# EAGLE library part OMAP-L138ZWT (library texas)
OMAP-L138 Low-Power Applications Processor Auto generated by make-symbol-device-package-bsdl.ulp Rev. 30 Source: sprm376a.bsm http://focus.ti.com/lit/ds/symlink/omap-l138.pdf Connect-List generated from OMAPL138ZWT.DEV Variant '' with connect-device-split-symbol-03.ulp
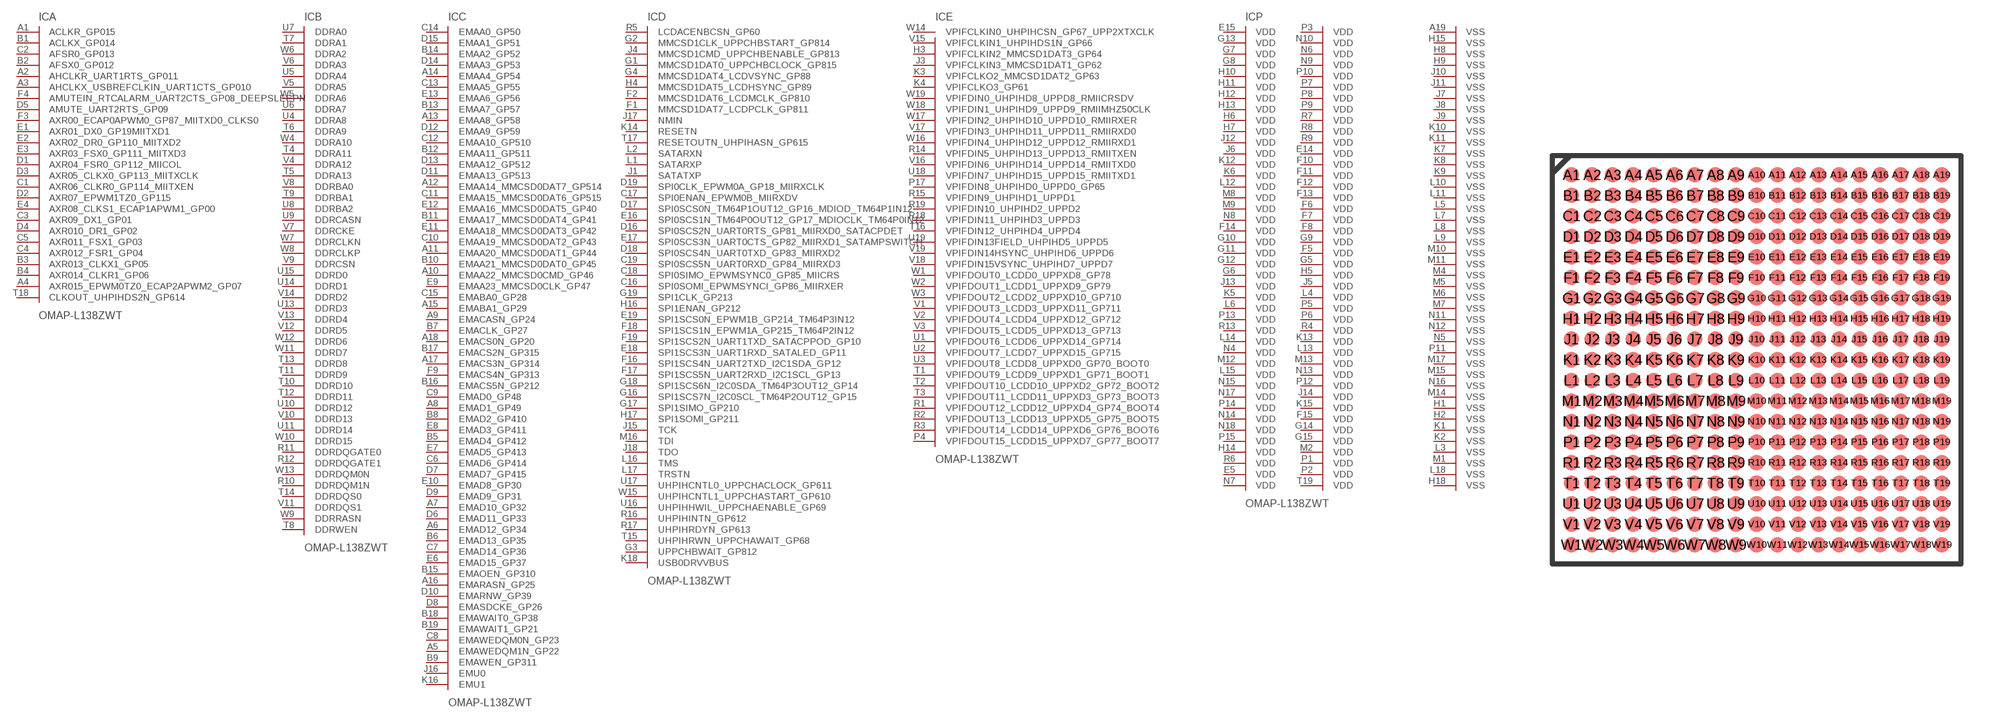
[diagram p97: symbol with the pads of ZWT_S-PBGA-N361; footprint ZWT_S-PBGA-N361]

Designator prefix IC; gates A=OMAPL138Z-A B=OMAPL138Z-B C=OMAPL138Z-C D=OMAPL138Z-D E=OMAPL138Z-E P=OMAPL138Z-P

## OMAP-L138ZWT (OC_FARNELL: unknown; OC_NEWARK: unknown)  [ZWT_S-PBGA-N361]
A1  A:ACLKR_GP015
A2  A:AHCLKR_UART1RTS_GP011
A3  A:AHCLKX_USBREFCLKIN_UART1CTS_GP010
A4  A:AXR015_EPWM0TZ0_ECAP2APWM2_GP07
A5  C:EMAWEDQM1N_GP22
A6  C:EMAD12_GP34
A7  C:EMAD10_GP32
A8  C:EMAD1_GP49
A9  C:EMACASN_GP24
A10  C:EMAA22_MMCSD0CMD_GP46
A11  C:EMAA20_MMCSD0DAT1_GP44
A12  C:EMAA14_MMCSD0DAT7_GP514
A13  C:EMAA8_GP58
A14  C:EMAA4_GP54
A15  C:EMABA1_GP29
A16  C:EMARASN_GP25
A17  C:EMACS3N_GP314
A18  C:EMACS0N_GP20
A19  P:VSS  pwr
B1  A:ACLKX_GP014
B2  A:AFSX0_GP012
B3  A:AXR013_CLKX1_GP05
B4  A:AXR014_CLKR1_GP06
B5  C:EMAD4_GP412
B6  C:EMAD13_GP35
B7  C:EMACLK_GP27
B8  C:EMAD2_GP410
B9  C:EMAWEN_GP311
B10  C:EMAA21_MMCSD0DAT0_GP45
B11  C:EMAA17_MMCSD0DAT4_GP41
B12  C:EMAA11_GP511
B13  C:EMAA7_GP57
B14  C:EMAA2_GP52
B15  C:EMAOEN_GP310
B16  C:EMACS5N_GP212
B17  C:EMACS2N_GP315
B18  C:EMAWAIT0_GP38
B19  C:EMAWAIT1_GP21
C1  A:AXR06_CLKR0_GP114_MIITXEN
C2  A:AFSR0_GP013
C3  A:AXR09_DX1_GP01
C4  A:AXR012_FSR1_GP04
C5  A:AXR011_FSX1_GP03
C6  C:EMAD6_GP414
C7  C:EMAD14_GP36
C8  C:EMAWEDQM0N_GP23
C9  C:EMAD0_GP48
C10  C:EMAA19_MMCSD0DAT2_GP43
C11  C:EMAA15_MMCSD0DAT6_GP515
C12  C:EMAA10_GP510
C13  C:EMAA5_GP55
C14  C:EMAA0_GP50
C15  C:EMABA0_GP28
C16  D:SPI0SOMI_EPWMSYNCI_GP86_MIIRXER
C17  D:SPI0ENAN_EPWM0B_MIIRXDV
C18  D:SPI0SIMO_EPWMSYNC0_GP85_MIICRS
C19  D:SPI0SCS5N_UART0RXD_GP84_MIIRXD3
D1  A:AXR04_FSR0_GP112_MIICOL
D2  A:AXR07_EPWM1TZ0_GP115
D3  A:AXR05_CLKX0_GP113_MIITXCLK
D4  A:AXR010_DR1_GP02
D5  A:AMUTE_UART2RTS_GP09
D6  C:EMAD11_GP33
D7  C:EMAD7_GP415
D8  C:EMASDCKE_GP26
D9  C:EMAD9_GP31
D10  C:EMARNW_GP39
D11  C:EMAA13_GP513
D12  C:EMAA9_GP59
D13  C:EMAA12_GP512
D14  C:EMAA3_GP53
D15  C:EMAA1_GP51
D16  D:SPI0SCS2N_UART0RTS_GP81_MIIRXD0_SATACPDET
D17  D:SPI0SCS0N_TM64P1OUT12_GP16_MDIOD_TM64P1IN12
D18  D:SPI0SCS4N_UART0TXD_GP83_MIIRXD2
D19  D:SPI0CLK_EPWM0A_GP18_MIIRXCLK
E1  A:AXR01_DX0_GP19MIITXD1
E2  A:AXR02_DR0_GP110_MIITXD2
E3  A:AXR03_FSX0_GP111_MIITXD3
E4  A:AXR08_CLKS1_ECAP1APWM1_GP00
E5  P:VDD  pwr
E6  C:EMAD15_GP37
E7  C:EMAD5_GP413
E8  C:EMAD3_GP411
E9  C:EMAA23_MMCSD0CLK_GP47
E10  C:EMAD8_GP30
E11  C:EMAA18_MMCSD0DAT3_GP42
E12  C:EMAA16_MMCSD0DAT5_GP40
E13  C:EMAA6_GP56
E14  P:VDD  pwr
E15  P:VDD  pwr
E16  D:SPI0SCS1N_TM64P0OUT12_GP17_MDIOCLK_TM64P0IN12
E17  D:SPI0SCS3N_UART0CTS_GP82_MIIRXD1_SATAMPSWITCH
E18  D:SPI1SCS3N_UART1RXD_SATALED_GP11
E19  D:SPI1SCS0N_EPWM1B_GP214_TM64P3IN12
F1  D:MMCSD1DAT7_LCDPCLK_GP811
F2  D:MMCSD1DAT6_LCDMCLK_GP810
F3  A:AXR00_ECAP0APWM0_GP87_MIITXD0_CLKS0
F4  A:AMUTEIN_RTCALARM_UART2CTS_GP08_DEEPSLEEPN
F5  P:VDD  pwr
F6  P:VDD  pwr
F7  P:VDD  pwr
F8  P:VDD  pwr
F9  C:EMACS4N_GP313
F10  P:VDD  pwr
F11  P:VDD  pwr
F12  P:VDD  pwr
F13  P:VDD  pwr
F14  P:VDD  pwr
F15  P:VDD  pwr
F16  D:SPI1SCS4N_UART2TXD_I2C1SDA_GP12
F17  D:SPI1SCS5N_UART2RXD_I2C1SCL_GP13
F18  D:SPI1SCS1N_EPWM1A_GP215_TM64P2IN12
F19  D:SPI1SCS2N_UART1TXD_SATACPPOD_GP10
G1  D:MMCSD1DAT0_UPPCHBCLOCK_GP815
G2  D:MMCSD1CLK_UPPCHBSTART_GP814
G3  D:UPPCHBWAIT_GP812
G4  D:MMCSD1DAT4_LCDVSYNC_GP88
G5  P:VDD  pwr
G6  P:VDD  pwr
G7  P:VDD  pwr
G8  P:VDD  pwr
G9  P:VDD  pwr
G10  P:VDD  pwr
G11  P:VDD  pwr
G12  P:VDD  pwr
G13  P:VDD  pwr
G14  P:VDD  pwr
G15  P:VDD  pwr
G16  D:SPI1SCS7N_I2C0SCL_TM64P2OUT12_GP15
G17  D:SPI1SIMO_GP210
G18  D:SPI1SCS6N_I2C0SDA_TM64P3OUT12_GP14
G19  D:SPI1CLK_GP213
H1  P:VSS  pwr
H2  P:VSS  pwr
H3  E:VPIFCLKIN2_MMCSD1DAT3_GP64
H4  D:MMCSD1DAT5_LCDHSYNC_GP89
H5  P:VDD  pwr
H6  P:VDD  pwr
H7  P:VDD  pwr
H8  P:VSS  pwr
H9  P:VSS  pwr
H10  P:VDD  pwr
H11  P:VDD  pwr
H12  P:VDD  pwr
H13  P:VDD  pwr
H14  P:VDD  pwr
H15  P:VSS  pwr
H16  D:SPI1ENAN_GP212
H17  D:SPI1SOMI_GP211
H18  P:VSS  pwr
J1  D:SATATXP  hiz
J3  E:VPIFCLKIN3_MMCSD1DAT1_GP62
J4  D:MMCSD1CMD_UPPCHBENABLE_GP813
J5  P:VDD  pwr
J6  P:VDD  pwr
J7  P:VSS  pwr
J8  P:VSS  pwr
J9  P:VSS  pwr
J10  P:VSS  pwr
J11  P:VSS  pwr
J12  P:VDD  pwr
J13  P:VDD  pwr
J14  P:VDD  pwr
J15  D:TCK  in
J16  C:EMU0
J17  D:NMIN  in
J18  D:TDO  out
K1  P:VSS  pwr
K2  P:VSS  pwr
K3  E:VPIFCLKO2_MMCSD1DAT2_GP63
K4  E:VPIFCLKO3_GP61
K5  P:VDD  pwr
K6  P:VDD  pwr
K7  P:VSS  pwr
K8  P:VSS  pwr
K9  P:VSS  pwr
K10  P:VSS  pwr
K11  P:VSS  pwr
K12  P:VDD  pwr
K13  P:VDD  pwr
K14  D:RESETN  in
K15  P:VDD  pwr
K16  C:EMU1
K18  D:USB0DRVVBUS
L1  D:SATARXP  in
L2  D:SATARXN  in
L3  P:VSS  pwr
L4  P:VDD  pwr
L5  P:VSS  pwr
L6  P:VDD  pwr
L7  P:VSS  pwr
L8  P:VSS  pwr
L9  P:VSS  pwr
L10  P:VSS  pwr
L11  P:VSS  pwr
L12  P:VDD  pwr
L13  P:VDD  pwr
L14  P:VDD  pwr
L15  P:VDD  pwr
L16  D:TMS  in
L17  D:TRSTN  in
L18  P:VSS  pwr
M1  P:VSS  pwr
M2  P:VDD  pwr
M4  P:VSS  pwr
M5  P:VSS  pwr
M6  P:VSS  pwr
M7  P:VSS  pwr
M8  P:VDD  pwr
M9  P:VDD  pwr
M10  P:VSS  pwr
M11  P:VSS  pwr
M12  P:VDD  pwr
M13  P:VDD  pwr
M14  P:VSS  pwr
M15  P:VSS  pwr
M16  D:TDI  in
M17  P:VSS  pwr
N4  P:VDD  pwr
N5  P:VSS  pwr
N6  P:VDD  pwr
N7  P:VDD  pwr
N8  P:VDD  pwr
N9  P:VDD  pwr
N10  P:VDD  pwr
N11  P:VSS  pwr
N12  P:VSS  pwr
N13  P:VDD  pwr
N14  P:VDD  pwr
N15  P:VDD  pwr
N16  P:VSS  pwr
N17  P:VDD  pwr
N18  P:VDD  pwr
P1  P:VDD  pwr
P2  P:VDD  pwr
P3  P:VDD  pwr
P4  E:VPIFDOUT15_LCDD15_UPPXD7_GP77_BOOT7
P5  P:VDD  pwr
P6  P:VDD  pwr
P7  P:VDD  pwr
P8  P:VDD  pwr
P9  P:VDD  pwr
P10  P:VDD  pwr
P11  P:VSS  pwr
P12  P:VDD  pwr
P13  P:VDD  pwr
P14  P:VDD  pwr
P15  P:VDD  pwr
P17  E:VPIFDIN8_UHPIHD0_UPPD0_GP65
R1  E:VPIFDOUT12_LCDD12_UPPXD4_GP74_BOOT4
R2  E:VPIFDOUT13_LCDD13_UPPXD5_GP75_BOOT5
R3  E:VPIFDOUT14_LCDD14_UPPXD6_GP76_BOOT6
R4  P:VDD  pwr
R5  D:LCDACENBCSN_GP60
R6  P:VDD  pwr
R7  P:VDD  pwr
R8  P:VDD  pwr
R9  P:VDD  pwr
R10  B:DDRDQM1N
R11  B:DDRDQGATE0
R12  B:DDRDQGATE1
R13  P:VDD  pwr
R14  E:VPIFDIN5_UHPIHD13_UPPD13_RMIITXEN
R15  E:VPIFDIN9_UHPIHD1_UPPD1
R16  D:UHPIHINTN_GP612
R17  D:UHPIHRDYN_GP613
R18  E:VPIFDIN11_UHPIHD3_UPPD3
R19  E:VPIFDIN10_UHPIHD2_UPPD2
T1  E:VPIFDOUT9_LCDD9_UPPXD1_GP71_BOOT1
T2  E:VPIFDOUT10_LCDD10_UPPXD2_GP72_BOOT2
T3  E:VPIFDOUT11_LCDD11_UPPXD3_GP73_BOOT3
T4  B:DDRA11
T5  B:DDRA13
T6  B:DDRA9
T7  B:DDRA1
T8  B:DDRWEN
T9  B:DDRBA1
T10  B:DDRD10
T11  B:DDRD9
T12  B:DDRD11
T13  B:DDRD8
T14  B:DDRDQS0
T15  D:UHPIHRWN_UPPCHAWAIT_GP68
T16  E:VPIFDIN12_UHPIHD4_UPPD4
T17  D:RESETOUTN_UHPIHASN_GP615
T18  A:CLKOUT_UHPIHDS2N_GP614
T19  P:VDD  pwr
U1  E:VPIFDOUT6_LCDD6_UPPXD14_GP714
U2  E:VPIFDOUT7_LCDD7_UPPXD15_GP715
U3  E:VPIFDOUT8_LCDD8_UPPXD0_GP70_BOOT0
U4  B:DDRA8
U5  B:DDRA4
U6  B:DDRA7
U7  B:DDRA0
U8  B:DDRBA2
U9  B:DDRCASN
U10  B:DDRD12
U11  B:DDRD14
U13  B:DDRD3
U14  B:DDRD1
U15  B:DDRD0
U16  D:UHPIHHWIL_UPPCHAENABLE_GP69
U17  D:UHPIHCNTL0_UPPCHACLOCK_GP611
U18  E:VPIFDIN7_UHPIHD15_UPPD15_RMIITXD1
U19  E:VPIFDIN13FIELD_UHPIHD5_UPPD5
V1  E:VPIFDOUT3_LCDD3_UPPXD11_GP711
V2  E:VPIFDOUT4_LCDD4_UPPXD12_GP712
V3  E:VPIFDOUT5_LCDD5_UPPXD13_GP713
V4  B:DDRA12
V5  B:DDRA5
V6  B:DDRA3
V7  B:DDRCKE
V8  B:DDRBA0
V9  B:DDRCSN
V10  B:DDRD13
V11  B:DDRDQS1
V12  B:DDRD5
V13  B:DDRD4
V14  B:DDRD2
V15  E:VPIFCLKIN1_UHPIHDS1N_GP66
V16  E:VPIFDIN6_UHPIHD14_UPPD14_RMIITXD0
V17  E:VPIFDIN3_UHPIHD11_UPPD11_RMIIRXD0
V18  E:VPIFDIN15VSYNC_UHPIHD7_UPPD7
V19  E:VPIFDIN14HSYNC_UHPIHD6_UPPD6
W1  E:VPIFDOUT0_LCDD0_UPPXD8_GP78
W2  E:VPIFDOUT1_LCDD1_UPPXD9_GP79
W3  E:VPIFDOUT2_LCDD2_UPPXD10_GP710
W4  B:DDRA10
W5  B:DDRA6
W6  B:DDRA2
W7  B:DDRCLKN
W8  B:DDRCLKP
W9  B:DDRRASN
W10  B:DDRD15
W11  B:DDRD7
W12  B:DDRD6
W13  B:DDRDQM0N
W14  E:VPIFCLKIN0_UHPIHCSN_GP67_UPP2XTXCLK
W15  D:UHPIHCNTL1_UPPCHASTART_GP610
W16  E:VPIFDIN4_UHPIHD12_UPPD12_RMIIRXD1
W17  E:VPIFDIN2_UHPIHD10_UPPD10_RMIIRXER
W18  E:VPIFDIN1_UHPIHD9_UPPD9_RMIIMHZ50CLK
W19  E:VPIFDIN0_UHPIHD8_UPPD8_RMIICRSDV

## Footprint ZWT_S-PBGA-N361 (pad centres in mm)
ZWT (S-PBGA-N361) Auto generated by make-symbol-device-package-bsdl.ulp Rev. 30 Source: sprm376a.bsm http://focus.ti.com/lit/ds/symlink/omap-l138.pdf
smd 0.6 x 0.6: A1 -7.2,7.2; A2 -6.4,7.2; A3 -5.6,7.2; A4 -4.8,7.2; A5 -4,7.2; A6 -3.2,7.2; A7 -2.4,7.2; A8 -1.6,7.2; A9 -0.8,7.2; A10 0,7.2; A11 0.8,7.2; A12 1.6,7.2; A13 2.4,7.2; A14 3.2,7.2; A15 4,7.2; A16 4.8,7.2; A17 5.6,7.2; A18 6.4,7.2; A19 7.2,7.2; B1 -7.2,6.4; B2 -6.4,6.4; B3 -5.6,6.4; B4 -4.8,6.4; B5 -4,6.4; B6 -3.2,6.4; B7 -2.4,6.4; B8 -1.6,6.4; B9 -0.8,6.4; B10 0,6.4; B11 0.8,6.4; B12 1.6,6.4; B13 2.4,6.4; B14 3.2,6.4; B15 4,6.4; B16 4.8,6.4; B17 5.6,6.4; B18 6.4,6.4; B19 7.2,6.4; C1 -7.2,5.6; C2 -6.4,5.6; C3 -5.6,5.6; C4 -4.8,5.6; C5 -4,5.6; C6 -3.2,5.6; C7 -2.4,5.6; C8 -1.6,5.6; C9 -0.8,5.6; C10 0,5.6; C11 0.8,5.6; C12 1.6,5.6; C13 2.4,5.6; C14 3.2,5.6; C15 4,5.6; C16 4.8,5.6; C17 5.6,5.6; C18 6.4,5.6; C19 7.2,5.6; D1 -7.2,4.8; D2 -6.4,4.8; D3 -5.6,4.8; D4 -4.8,4.8; D5 -4,4.8; D6 -3.2,4.8; D7 -2.4,4.8; D8 -1.6,4.8; D9 -0.8,4.8; D10 0,4.8; D11 0.8,4.8; D12 1.6,4.8; D13 2.4,4.8; D14 3.2,4.8; D15 4,4.8; D16 4.8,4.8; D17 5.6,4.8; D18 6.4,4.8; D19 7.2,4.8; E1 -7.2,4; E2 -6.4,4; E3 -5.6,4; E4 -4.8,4; E5 -4,4; E6 -3.2,4; E7 -2.4,4; E8 -1.6,4; E9 -0.8,4; E10 0,4; E11 0.8,4; E12 1.6,4; E13 2.4,4; E14 3.2,4; E15 4,4; E16 4.8,4; E17 5.6,4; E18 6.4,4; E19 7.2,4; F1 -7.2,3.2; F2 -6.4,3.2; F3 -5.6,3.2; F4 -4.8,3.2; F5 -4,3.2; F6 -3.2,3.2; F7 -2.4,3.2; F8 -1.6,3.2; F9 -0.8,3.2; F10 0,3.2; F11 0.8,3.2; F12 1.6,3.2; F13 2.4,3.2; F14 3.2,3.2; F15 4,3.2; F16 4.8,3.2; F17 5.6,3.2; F18 6.4,3.2; F19 7.2,3.2; G1 -7.2,2.4; G2 -6.4,2.4; G3 -5.6,2.4; G4 -4.8,2.4; G5 -4,2.4; G6 -3.2,2.4; G7 -2.4,2.4; G8 -1.6,2.4; G9 -0.8,2.4; G10 0,2.4; G11 0.8,2.4; G12 1.6,2.4; G13 2.4,2.4; G14 3.2,2.4; G15 4,2.4; G16 4.8,2.4; G17 5.6,2.4; G18 6.4,2.4; G19 7.2,2.4; H1 -7.2,1.6; H2 -6.4,1.6; H3 -5.6,1.6; H4 -4.8,1.6; H5 -4,1.6; H6 -3.2,1.6; H7 -2.4,1.6; H8 -1.6,1.6; H9 -0.8,1.6; H10 0,1.6; H11 0.8,1.6; H12 1.6,1.6; H13 2.4,1.6; H14 3.2,1.6; H15 4,1.6; H16 4.8,1.6; H17 5.6,1.6; H18 6.4,1.6; H19 7.2,1.6; J1 -7.2,0.8; J2 -6.4,0.8; J3 -5.6,0.8; J4 -4.8,0.8; J5 -4,0.8; J6 -3.2,0.8; J7 -2.4,0.8; J8 -1.6,0.8; J9 -0.8,0.8; J10 0,0.8; J11 0.8,0.8; J12 1.6,0.8; J13 2.4,0.8; J14 3.2,0.8; J15 4,0.8; J16 4.8,0.8; J17 5.6,0.8; J18 6.4,0.8; J19 7.2,0.8; K1 -7.2,0; K2 -6.4,0; K3 -5.6,0; K4 -4.8,0; K5 -4,0; K6 -3.2,0; K7 -2.4,0; K8 -1.6,0; K9 -0.8,0; K10 0,0; K11 0.8,0; K12 1.6,0; K13 2.4,0; K14 3.2,0; K15 4,0; K16 4.8,0; K17 5.6,0; K18 6.4,0; K19 7.2,0; L1 -7.2,-0.8; L2 -6.4,-0.8; L3 -5.6,-0.8; L4 -4.8,-0.8; L5 -4,-0.8; L6 -3.2,-0.8; L7 -2.4,-0.8; L8 -1.6,-0.8; L9 -0.8,-0.8; L10 0,-0.8; L11 0.8,-0.8; L12 1.6,-0.8; L13 2.4,-0.8; L14 3.2,-0.8; L15 4,-0.8; L16 4.8,-0.8; L17 5.6,-0.8; L18 6.4,-0.8; L19 7.2,-0.8; M1 -7.2,-1.6; M2 -6.4,-1.6; M3 -5.6,-1.6; M4 -4.8,-1.6; M5 -4,-1.6; M6 -3.2,-1.6; M7 -2.4,-1.6; M8 -1.6,-1.6; M9 -0.8,-1.6; M10 0,-1.6; M11 0.8,-1.6; M12 1.6,-1.6; M13 2.4,-1.6; M14 3.2,-1.6; M15 4,-1.6; M16 4.8,-1.6; M17 5.6,-1.6; M18 6.4,-1.6; M19 7.2,-1.6; N1 -7.2,-2.4; N2 -6.4,-2.4; N3 -5.6,-2.4; N4 -4.8,-2.4; N5 -4,-2.4; N6 -3.2,-2.4; N7 -2.4,-2.4; N8 -1.6,-2.4; N9 -0.8,-2.4; N10 0,-2.4; N11 0.8,-2.4; N12 1.6,-2.4; N13 2.4,-2.4; N14 3.2,-2.4; N15 4,-2.4; N16 4.8,-2.4; N17 5.6,-2.4; N18 6.4,-2.4; N19 7.2,-2.4; P1 -7.2,-3.2; P2 -6.4,-3.2; P3 -5.6,-3.2; P4 -4.8,-3.2; P5 -4,-3.2; P6 -3.2,-3.2; P7 -2.4,-3.2; P8 -1.6,-3.2; P9 -0.8,-3.2; P10 0,-3.2; P11 0.8,-3.2; P12 1.6,-3.2; P13 2.4,-3.2; P14 3.2,-3.2; P15 4,-3.2; P16 4.8,-3.2; P17 5.6,-3.2; P18 6.4,-3.2; P19 7.2,-3.2; R1 -7.2,-4; R2 -6.4,-4; R3 -5.6,-4; R4 -4.8,-4; R5 -4,-4; R6 -3.2,-4; R7 -2.4,-4; R8 -1.6,-4; R9 -0.8,-4; R10 0,-4; R11 0.8,-4; R12 1.6,-4; R13 2.4,-4; R14 3.2,-4; R15 4,-4; R16 4.8,-4; R17 5.6,-4; R18 6.4,-4; R19 7.2,-4; T1 -7.2,-4.8; T2 -6.4,-4.8; T3 -5.6,-4.8; T4 -4.8,-4.8; T5 -4,-4.8; T6 -3.2,-4.8; T7 -2.4,-4.8; T8 -1.6,-4.8; T9 -0.8,-4.8; T10 0,-4.8; T11 0.8,-4.8; T12 1.6,-4.8; T13 2.4,-4.8; T14 3.2,-4.8; T15 4,-4.8; T16 4.8,-4.8; T17 5.6,-4.8; T18 6.4,-4.8; T19 7.2,-4.8; U1 -7.2,-5.6; U2 -6.4,-5.6; U3 -5.6,-5.6; U4 -4.8,-5.6; U5 -4,-5.6; U6 -3.2,-5.6; U7 -2.4,-5.6; U8 -1.6,-5.6; U9 -0.8,-5.6; U10 0,-5.6; U11 0.8,-5.6; U12 1.6,-5.6; U13 2.4,-5.6; U14 3.2,-5.6; U15 4,-5.6; U16 4.8,-5.6; U17 5.6,-5.6; U18 6.4,-5.6; U19 7.2,-5.6; V1 -7.2,-6.4; V2 -6.4,-6.4; V3 -5.6,-6.4; V4 -4.8,-6.4; V5 -4,-6.4; V6 -3.2,-6.4; V7 -2.4,-6.4; V8 -1.6,-6.4; V9 -0.8,-6.4; V10 0,-6.4; V11 0.8,-6.4; V12 1.6,-6.4; V13 2.4,-6.4; V14 3.2,-6.4; V15 4,-6.4; V16 4.8,-6.4; V17 5.6,-6.4; V18 6.4,-6.4; V19 7.2,-6.4; W1 -7.2,-7.2; W2 -6.4,-7.2; W3 -5.6,-7.2; W4 -4.8,-7.2; W5 -4,-7.2; W6 -3.2,-7.2; W7 -2.4,-7.2; W8 -1.6,-7.2; W9 -0.8,-7.2; W10 0,-7.2; W11 0.8,-7.2; W12 1.6,-7.2; W13 2.4,-7.2; W14 3.2,-7.2; W15 4,-7.2; W16 4.8,-7.2; W17 5.6,-7.2; W18 6.4,-7.2; W19 7.2,-7.2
